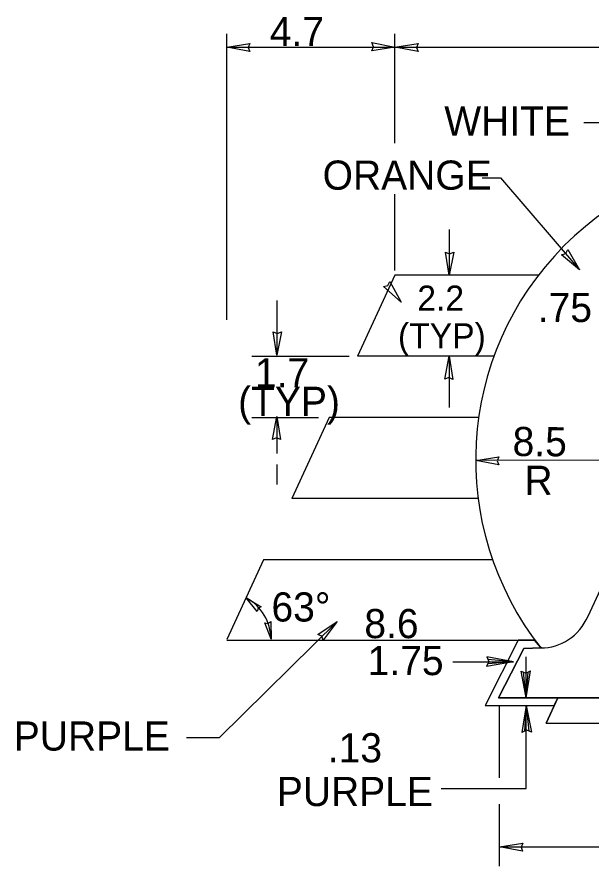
# Model space of a CAD drawing. Extents: x 10268197 to 10269179, y 2141503 to 2142677.
# Drawn here: x 10268587.21 to 10268600.98, y 2142087.2 to 2142107.58 of the extents above; entities that cross this region are included whole.
import ezdxf

# ---------------------------------------------------------------- set-up
doc = ezdxf.new("R2010")
doc.units = 0
for name, color, linetype in [('1', 7, 'Continuous'), ('2', 7, 'Continuous'), ('3', 7, 'Continuous'), ('52', 7, 'Continuous'), ('56', 7, 'Continuous')]:
    doc.layers.add(name, color=color, linetype=linetype)

msp = doc.modelspace()

# ---------------------------------------------------------------- linework, layer by layer
at = {"layer": '1'}
for p, q in [((10268592.239, 2142100.315), (10268592.239, 2142107.18)), ((10268596.278, 2142104.552), (10268596.278, 2142107.18)), ((10268592.239, 2142106.859), (10268596.278, 2142106.859)), ((10268596.278, 2142106.859), (10268637.974, 2142106.859)), ((10268596.278, 2142101.493), (10268596.278, 2142103.329)), ((10268597.582, 2142102.481), (10268597.582, 2142101.382)), ((10268596.278, 2142101.382), (10268595.381, 2142099.439)), ((10268599.719, 2142101.382), (10268596.278, 2142101.382)), ((10268593.445, 2142100.778), (10268593.445, 2142099.467)), ((10268592.839, 2142099.439), (10268595.175, 2142099.439)), ((10268598.654, 2142099.439), (10268595.381, 2142099.439)), ((10268597.582, 2142099.439), (10268597.582, 2142098.205)), ((10268592.839, 2142097.966), (10268594.446, 2142097.966)), ((10268593.445, 2142097.993), (10268593.445, 2142097.102)), ((10268594.701, 2142097.966), (10268593.803, 2142096.023)), ((10268598.287, 2142097.966), (10268594.701, 2142097.966)), ((10268605.504, 2142096.949), (10268598.216, 2142096.938)), ((10268593.445, 2142096.843), (10268593.445, 2142096.355)), ((10268598.276, 2142096.023), (10268593.803, 2142096.023)), ((10268593.123, 2142094.55), (10268592.239, 2142092.637)), ((10268598.603, 2142094.55), (10268593.123, 2142094.55)), ((10268592.07, 2142090.29), (10268594.891, 2142093.073)), ((10268592.239, 2142092.624), (10268599.211, 2142092.624)), ((10268597.667, 2142092.103), (10268599.124, 2142092.103)), ((10268599.429, 2142091.236), (10268599.429, 2142092.226)), ((10268599.429, 2142091.295), (10268599.429, 2142091.928)), ((10268600.185, 2142091.236), (10268599.906, 2142090.632)), ((10268600.126, 2142091.108), (10268600.185, 2142091.236)), ((10268608.023, 2142091.236), (10268600.185, 2142091.236)), ((10268598.789, 2142089.318), (10268598.789, 2142091.047)), ((10268599.429, 2142089.063), (10268599.429, 2142091.056)), ((10268599.906, 2142090.632), (10268608.561, 2142090.632)), ((10268591.277, 2142090.29), (10268592.07, 2142090.29)), ((10268597.387, 2142089.063), (10268599.429, 2142089.063)), ((10268598.789, 2142087.201), (10268598.789, 2142088.685)), ((10268598.789, 2142087.662), (10268608.023, 2142087.662))]:
    msp.add_line(p, q, dxfattribs=at)
for points in [[(10268600.808, 2142105.052), (10268601.286, 2142105.052), (10268604.718, 2142101.83)], [(10268598.368, 2142103.718), (10268598.807, 2142103.718), (10268600.705, 2142101.509)]]:
    msp.add_lwpolyline(points, dxfattribs=at)
msp.add_arc((10268592.147, 2142092.627), 1.158, 0.8256, 61.0937, dxfattribs=at)
at = {"layer": '2'}
for p, q in [((10268600.913, 2142093.196), (10268604.387, 2142100.777)), ((10268599.237, 2142092.624), (10268598.44, 2142091.056)), ((10268599.237, 2142092.624), (10268599.641, 2142092.624)), ((10268599.368, 2142092.425), (10268598.763, 2142091.236)), ((10268599.781, 2142092.437), (10268599.368, 2142092.425)), ((10268598.763, 2142091.236), (10268608.023, 2142091.236)), ((10268599.906, 2142090.632), (10268600.185, 2142091.236)), ((10268598.44, 2142091.056), (10268600.102, 2142091.056)), ((10268599.906, 2142090.632), (10268608.561, 2142090.632))]:
    msp.add_line(p, q, dxfattribs=at)
msp.add_arc((10268605.504, 2142096.949), 7.288, 51.9618, 218.2529, dxfattribs=at)
msp.add_ellipse((10268599.804, 2142093.826), major_axis=(0, 1.387), ratio=0.897229, start_param=3.121696, end_param=4.241135, dxfattribs=at)
at = {"layer": '3'}
msp.add_lwpolyline([(10268599.629, 2142092.624), (10268599.237, 2142092.624), (10268598.44, 2142091.056), (10268600.102, 2142091.056), (10268600.185, 2142091.236), (10268598.763, 2142091.236), (10268599.368, 2142092.425), (10268599.792, 2142092.437), (10268599.773, 2142092.457)], close=True, dxfattribs=at)
at = {"layer": '52'}
for p, q in [((10268598.529, 2142092.107), (10268598.478, 2142091.994)), ((10268599.124, 2142092.103), (10268598.478, 2142091.994)), ((10268599.124, 2142092.103), (10268598.48, 2142092.222)), ((10268598.48, 2142092.222), (10268598.529, 2142092.107)), ((10268599.124, 2142092.103), (10268598.505, 2142092.162)), ((10268599.124, 2142092.103), (10268598.505, 2142092.054)), ((10268599.429, 2142091.236), (10268599.304, 2142091.878)), ((10268599.304, 2142091.878), (10268599.419, 2142091.831)), ((10268599.429, 2142091.236), (10268599.365, 2142091.854)), ((10268599.419, 2142091.831), (10268599.532, 2142091.883)), ((10268599.429, 2142091.236), (10268599.532, 2142091.883)), ((10268599.429, 2142091.236), (10268599.472, 2142091.855)), ((10268599.429, 2142091.056), (10268599.326, 2142090.41)), ((10268599.429, 2142091.056), (10268599.386, 2142090.437)), ((10268599.429, 2142091.056), (10268599.554, 2142090.413)), ((10268599.429, 2142091.056), (10268599.494, 2142090.438)), ((10268599.439, 2142090.461), (10268599.326, 2142090.41)), ((10268599.554, 2142090.413), (10268599.439, 2142090.461))]:
    msp.add_line(p, q, dxfattribs=at)
for points in [[(10268592.239, 2142106.859), (10268592.796, 2142106.947), (10268592.754, 2142106.851), (10268592.792, 2142106.752)], [(10268596.278, 2142106.859), (10268595.722, 2142106.771), (10268595.764, 2142106.867), (10268595.726, 2142106.966)], [(10268596.278, 2142106.859), (10268596.835, 2142106.947), (10268596.793, 2142106.851), (10268596.831, 2142106.752)], [(10268597.582, 2142101.382), (10268597.494, 2142101.938), (10268597.589, 2142101.896), (10268597.688, 2142101.934)], [(10268600.705, 2142101.509), (10268600.276, 2142101.874), (10268600.376, 2142101.905), (10268600.426, 2142101.998)], [(10268596.428, 2142100.739), (10268596.003, 2142101.109), (10268596.103, 2142101.138), (10268596.154, 2142101.231)], [(10268593.445, 2142099.467), (10268593.357, 2142100.024), (10268593.453, 2142099.982), (10268593.552, 2142100.02)], [(10268597.582, 2142099.439), (10268597.669, 2142098.883), (10268597.574, 2142098.925), (10268597.475, 2142098.887)], [(10268593.445, 2142097.993), (10268593.533, 2142097.436), (10268593.438, 2142097.478), (10268593.338, 2142097.44)], [(10268598.216, 2142096.938), (10268598.772, 2142097.027), (10268598.73, 2142096.931), (10268598.769, 2142096.832)], [(10268592.706, 2142093.641), (10268593.069, 2142093.423), (10268592.998, 2142093.388), (10268592.972, 2142093.314)], [(10268593.308, 2142092.645), (10268593.154, 2142093.039), (10268593.23, 2142093.022), (10268593.297, 2142093.067)], [(10268594.891, 2142093.073), (10268594.556, 2142092.62), (10268594.519, 2142092.717), (10268594.423, 2142092.761)], [(10268598.789, 2142087.662), (10268599.345, 2142087.75), (10268599.304, 2142087.655), (10268599.342, 2142087.556)]]:
    msp.add_lwpolyline(points, close=True, dxfattribs=at)
at = {"layer": '56'}
msp.add_lwpolyline([(10268596.422, 2142100.741), (10268596.428, 2142100.739), (10268596.422, 2142100.744), (10268596.424, 2142100.743), (10268596.424, 2142100.743), (10268596.424, 2142100.743), (10268596.426, 2142100.741), (10268596.424, 2142100.742), (10268596.426, 2142100.741), (10268596.422, 2142100.742), (10268596.424, 2142100.741), (10268596.422, 2142100.741), (10268596.422, 2142100.741), (10268596.424, 2142100.742), (10268596.422, 2142100.744)], dxfattribs=at)
msp.add_lwpolyline([(10268596.422, 2142100.741), (10268596.428, 2142100.739), (10268596.422, 2142100.744), (10268596.424, 2142100.743), (10268596.424, 2142100.743), (10268596.424, 2142100.743), (10268596.426, 2142100.741), (10268596.424, 2142100.742), (10268596.426, 2142100.741), (10268596.422, 2142100.742), (10268596.424, 2142100.741), (10268596.422, 2142100.741), (10268596.422, 2142100.741), (10268596.424, 2142100.742), (10268596.422, 2142100.744)], dxfattribs=at)
msp.add_lwpolyline([(10268596.422, 2142100.741), (10268596.428, 2142100.739), (10268596.422, 2142100.744), (10268596.424, 2142100.743), (10268596.424, 2142100.743), (10268596.424, 2142100.743), (10268596.426, 2142100.741), (10268596.424, 2142100.742), (10268596.426, 2142100.741), (10268596.422, 2142100.742), (10268596.424, 2142100.741), (10268596.422, 2142100.741), (10268596.422, 2142100.741), (10268596.424, 2142100.742), (10268596.422, 2142100.744)], dxfattribs=at)

# ---------------------------------------------------------------- texts
at = {"layer": '1'}
for s, height, p in [('4.7', 0.7, (10268593.275, 2142106.881)), ('WHITE', 0.7, (10268597.462, 2142104.734)), ('ORANGE', 0.7, (10268594.542, 2142103.435)), ('2.2', 0.6037, (10268596.814, 2142100.53)), ('.75', 0.7, (10268599.705, 2142100.258)), ('(TYP)', 0.6037, (10268596.35, 2142099.626)), ('1.7', 0.7, (10268592.918, 2142098.689)), ('(TYP)', 0.7, (10268592.514, 2142098.006)), ('63°', 0.7, (10268593.314, 2142093.07)), ('8.6', 0.7, (10268595.543, 2142092.671)), ('1.75', 0.7, (10268595.623, 2142091.783)), ('PURPLE', 0.7, (10268587.13, 2142089.972)), ('.13', 0.7, (10268594.666, 2142089.69)), ('PURPLE', 0.7, (10268593.443, 2142088.64))]:
    msp.add_text(s, height=height, dxfattribs=at).set_placement(p)
for s, rotation, p in [('8.5', 359.5763, (10268599.099, 2142097.043)), ('R', 0.3852, (10268599.387, 2142096.107))]:
    msp.add_text(s, height=0.7, rotation=rotation, dxfattribs=at).set_placement(p)

doc.saveas('drawing.dxf')
